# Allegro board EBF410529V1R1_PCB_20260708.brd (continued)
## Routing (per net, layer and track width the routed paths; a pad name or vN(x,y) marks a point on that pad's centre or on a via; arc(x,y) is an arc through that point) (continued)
MIPI_DPHY_CSI3_RX_D0P: length 78.5
  TOP w0.107: J18.11 6.56,55.37 7.29,55.37 arc(7.35,55.38) 7.4,55.42 7.42,55.43 arc(7.47,55.46) 7.53,55.48 11.25,55.48 arc(11.96,55.34) 12.56,54.93 12.89,54.6 arc(13.3,54) 13.44,53.29 13.44,52.3 arc(13.49,52.02) 13.65,51.78 15.72,49.71 arc(16.2,49.51) 16.67,49.71 17.01,50.05 arc(17.19,50.12) 17.37,50.05 arc(17.45,49.85) 17.37,49.65 17.04,49.32 arc(16.85,48.86) 17.04,48.39 17.06,48.37 arc(17.52,48.18) 17.98,48.37 19.44,49.83 arc(19.63,49.91) 19.82,49.83 arc(19.9,49.64) 19.82,49.45 18.29,47.92 arc(18.13,47.53) 18.29,47.14 18.29,47.14 arc(18.64,46.9) 19.06,46.82 19.62,46.82 arc(19.78,46.79) 19.92,46.7 v1(20.06,46.56) ; J3.184 v1(62.19,62.44)
  ART03 w0.102: v1(62.19,62.44) 62.19,62.33 arc(62.21,62.25) 62.25,62.18 62.5,61.93 arc(62.58,61.81) 62.61,61.67 62.61,58.51 arc(62.47,57.79) 62.06,57.19 54.87,49.99 arc(54.53,49.76) 54.12,49.68 25.3,49.68 arc(24.63,49.55) 24.06,49.17 22.9,48.01 arc(22.48,47.72) 21.98,47.62 21.85,47.62 arc(21.5,47.55) 21.2,47.35 20.85,47.01 arc(20.64,46.87) 20.41,46.82 arc(20.33,46.81) 20.26,46.76 v1(20.06,46.56)
MIPI_DPHY_CSI3_RX_D1N: length 80.2
  TOP w0.107: J18.8 7.29,53.87 arc(7.35,53.86) 7.4,53.82 7.42,53.81 arc(7.47,53.77) 7.53,53.76 8.36,53.76 arc(8.74,53.6) 8.91,53.21 8.91,53.01 arc(8.98,52.84) 9.16,52.76 9.17,52.76 arc(9.36,52.84) 9.44,53.03 9.44,53.21 arc(9.6,53.6) 9.99,53.76 11.17,53.76 arc(11.54,53.69) 11.84,53.48 11.86,53.47 arc(12.07,53.16) 12.14,52.8 12.14,52.01 arc(12.25,51.45) 12.56,50.99 12.72,50.83 arc(12.9,50.4) 12.72,49.97 12.44,49.69 arc(12.36,49.5) 12.44,49.31 arc(12.62,49.23) 12.81,49.31 13.1,49.6 arc(13.53,49.77) 13.95,49.6 17.12,46.43 arc(17.35,45.87) 17.12,45.3 16.6,44.78 arc(16.52,44.59) 16.6,44.4 arc(16.8,44.32) 17,44.4 17.69,45.09 arc(18.07,45.25) 18.46,45.09 18.47,45.08 arc(18.67,44.95) 18.91,44.9 19.62,44.9 arc(19.78,44.93) 19.92,45.02 v1(20.06,45.16) ; J3.190 63.69,62.13 v1(63.19,61.63)
  ART03 w0.102: v1(20.06,45.16) 20.22,45 arc(20.39,44.89) 20.59,44.85 21.11,44.85 arc(21.23,44.9) 21.29,45.02 21.29,46.24 arc(21.53,46.82) 22.11,47.07 22.19,47.07 arc(22.64,47.16) 23.03,47.42 24.09,48.48 arc(24.75,48.92) 25.53,49.07 53.89,49.07 arc(54.63,49.22) 55.25,49.64 62.71,57.1 arc(63.16,57.77) 63.32,58.57 63.32,59.65 arc(63.29,59.73) 63.21,59.76 arc(63.13,59.79) 63.09,59.88 63.09,60.05 arc(63.13,60.13) 63.21,60.17 arc(63.29,60.2) 63.32,60.28 63.32,60.46 arc(63.29,60.54) 63.21,60.57 arc(63.13,60.61) 63.09,60.69 63.09,60.87 arc(63.13,60.95) 63.21,60.98 arc(63.29,61.01) 63.32,61.09 63.32,61.42 arc(63.31,61.49) 63.26,61.56 v1(63.19,61.63)
MIPI_DPHY_CSI3_RX_D1P: length 80.1
  TOP w0.107: J18.7 6.56,53.37 7.29,53.37 arc(7.35,53.38) 7.4,53.42 7.42,53.43 arc(7.47,53.46) 7.53,53.48 8.36,53.48 arc(8.54,53.4) 8.62,53.21 8.62,53.01 arc(8.78,52.63) 9.16,52.48 9.17,52.48 arc(9.56,52.64) 9.72,53.03 9.72,53.21 arc(9.8,53.4) 9.99,53.48 11.17,53.48 arc(11.43,53.43) 11.64,53.28 11.66,53.26 arc(11.81,53.05) 11.86,52.8 11.86,52.01 arc(11.99,51.35) 12.36,50.79 12.52,50.63 arc(12.62,50.4) 12.52,50.18 12.23,49.89 arc(12.07,49.5) 12.23,49.11 arc(12.62,48.95) 13.01,49.11 13.3,49.4 arc(13.53,49.49) 13.75,49.4 16.92,46.23 arc(17.07,45.87) 16.92,45.5 16.39,44.98 arc(16.23,44.59) 16.39,44.2 16.4,44.2 arc(16.8,44.03) 17.2,44.2 17.89,44.88 arc(18.07,44.96) 18.26,44.88 18.27,44.88 arc(18.56,44.68) 18.91,44.62 19.85,44.62 arc(20,44.55) 20.06,44.41 v1(20.06,44.35) ; J3.188 v1(63.19,62.44)
  ART03 w0.102: v1(20.06,44.35) 20.17,44.47 arc(20.28,44.54) 20.41,44.57 21.11,44.57 arc(21.43,44.7) 21.56,45.02 21.56,46.24 arc(21.72,46.63) 22.11,46.79 22.19,46.79 arc(22.75,46.9) 23.23,47.22 24.29,48.28 arc(24.86,48.66) 25.53,48.79 53.89,48.79 arc(54.73,48.96) 55.45,49.44 62.91,56.9 arc(63.42,57.67) 63.6,58.57 63.6,61.66 arc(63.58,61.79) 63.5,61.9 63.27,62.13 arc(63.21,62.22) 63.19,62.31 v1(63.19,62.44)
MIPI_DPHY_CSI4_RX_CLKN: length 77.7
  TOP w0.107: v1(60.73,58.48) 60.88,58.63 arc(61.02,58.73) 61.19,58.76 66.66,58.76 arc(67.2,58.87) 67.65,59.17 67.67,59.19 arc(67.98,59.64) 68.08,60.18 68.08,62.47 arc(68.1,62.53) 68.13,62.58 68.14,62.6 arc(68.18,62.65) 68.19,62.71 J3.208
  ART03 w0.102: v1(7.82,38.4) 7.96,38.54 arc(8.04,38.6) 8.13,38.64 arc(8.18,38.64) 8.23,38.63 14.34,38.63 arc(14.83,38.73) 15.25,39.01 18.28,42.04 arc(18.72,42.7) 18.87,43.47 18.87,47.51 arc(18.9,47.65) 18.98,47.77 19.32,48.11 arc(19.8,48.43) 20.36,48.54 21.03,48.54 arc(21.81,48.69) 22.46,49.13 23.57,50.24 arc(24.13,50.62) 24.81,50.75 53.47,50.75 arc(54.12,50.88) 54.67,51.25 59.98,56.55 arc(60.34,57.09) 60.47,57.73 60.47,58.04 arc(60.5,58.2) 60.59,58.34 v1(60.73,58.48)
  BOTTOM w0.107: v1(7.82,38.4) 7.82,38.51 arc(7.78,38.61) 7.67,38.66 7.53,38.66 arc(7.47,38.65) 7.42,38.61 7.4,38.6 arc(7.35,38.56) 7.29,38.55 J17.10
MIPI_DPHY_CSI4_RX_CLKP: length 77.7
  TOP w0.107: v1(59.92,58.48) 60.04,58.48 arc(60.13,58.5) 60.2,58.55 60.4,58.75 arc(60.73,58.97) 61.11,59.04 66.66,59.04 arc(67.09,59.13) 67.45,59.37 67.47,59.39 arc(67.71,59.75) 67.8,60.18 67.8,62.47 arc(67.79,62.53) 67.75,62.58 67.74,62.6 arc(67.7,62.65) 67.69,62.71 J3.206
  ART03 w0.102: v1(7.82,39.2) 8.03,39 arc(8.1,38.94) 8.18,38.92 arc(8.2,38.91) 8.23,38.91 14.34,38.91 arc(14.72,38.99) 15.05,39.21 18.08,42.24 arc(18.46,42.81) 18.59,43.47 18.59,47.51 arc(18.64,47.76) 18.78,47.97 19.12,48.31 arc(19.69,48.69) 20.36,48.82 21.03,48.82 arc(21.7,48.95) 22.27,49.33 23.37,50.43 arc(24.03,50.87) 24.81,51.03 53.47,51.03 arc(54.02,51.14) 54.47,51.44 59.78,56.75 arc(60.08,57.2) 60.19,57.73 60.19,58.04 arc(60.15,58.2) 60.06,58.34 v1(59.92,58.48)
  BOTTOM w0.107: v1(7.82,39.2) 7.82,39.06 arc(7.78,38.98) 7.7,38.94 7.53,38.94 arc(7.47,38.95) 7.42,38.99 7.4,39 arc(7.35,39.04) 7.29,39.05 J17.9
MIPI_DPHY_CSI4_RX_D0N: length 83.9
  TOP w0.107: J3.200 66.19,62.71 arc(66.18,62.65) 66.14,62.6 66.13,62.58 arc(66.1,62.53) 66.08,62.47 66.08,61.98 66.08,61.1 arc(65.94,60.75) 65.59,60.61 60.93,60.61 arc(60.86,60.59) 60.8,60.55 v1(60.73,60.48)
  ART03 w0.102: v1(5.05,37.4) 5.05,37.51 arc(5.06,37.6) 5.11,37.68 5.21,37.77 arc(5.38,37.89) 5.58,37.92 5.67,37.92 arc(5.94,37.98) 6.17,38.13 8.58,40.55 arc(8.69,40.62) 8.81,40.64 12.94,40.64 arc(13.12,40.6) 13.27,40.5 arc(13.5,40.4) 13.75,40.36 13.97,40.36 arc(14.41,40.45) 14.78,40.7 16.63,42.55 arc(17.16,43.34) 17.35,44.28 17.35,47.71 arc(17.48,48.38) 17.86,48.95 18.56,49.65 arc(19.13,50.03) 19.8,50.16 20.67,50.16 arc(20.95,50.22) 21.18,50.37 22.64,51.84 arc(23.21,52.22) 23.88,52.35 41.71,52.35 arc(42.03,52.48) 42.16,52.81 42.16,53.52 arc(42.18,53.61) 42.23,53.69 42.25,53.7 arc(42.32,53.75) 42.41,53.77 42.51,53.77 arc(42.67,53.7) 42.74,53.54 42.74,53.16 arc(43.27,52.63) 43.8,53.16 43.8,53.52 arc(44.06,53.77) 44.31,53.52 44.31,53.16 arc(44.85,52.63) 45.38,53.16 45.38,53.64 arc(45.45,53.82) 45.63,53.9 52.53,53.9 arc(52.63,53.88) 52.72,53.82 53.18,53.36 arc(53.91,53.06) 54.63,53.36 58.1,56.83 arc(58.47,57.38) 58.6,58.04 58.6,59.58 arc(58.64,59.75) 58.73,59.9 58.75,59.91 arc(58.9,60.01) 59.07,60.05 59.87,60.05 arc(60.06,60.08) 60.21,60.19 60.44,60.41 arc(60.52,60.46) 60.61,60.48 v1(60.73,60.48)
  BOTTOM w0.107: J17.12 5.84,37.55 arc(5.77,37.56) 5.71,37.6 5.68,37.63 arc(5.65,37.65) 5.61,37.66 5.31,37.66 arc(5.12,37.58) v1(5.05,37.4)
MIPI_DPHY_CSI4_RX_D0P: length 83.7
  TOP w0.107: v1(59.92,60.48) 60.05,60.48 arc(60.14,60.5) 60.23,60.56 60.47,60.8 arc(60.57,60.87) 60.69,60.89 64.56,60.89 arc(64.65,60.93) 64.68,61.01 arc(64.72,61.1) 64.81,61.14 64.99,61.14 arc(65.07,61.1) 65.11,61.01 arc(65.15,60.93) 65.23,60.89 65.59,60.89 arc(65.74,60.95) 65.8,61.1 65.8,62.47 arc(65.79,62.53) 65.75,62.58 65.74,62.6 arc(65.7,62.65) 65.69,62.71 J3.198
  ART03 w0.102: v1(59.92,60.48) 59.84,60.4 arc(59.76,60.34) 59.66,60.33 59.07,60.33 arc(58.79,60.27) 58.55,60.11 58.54,60.09 arc(58.38,59.86) 58.32,59.58 58.32,59.35 arc(58.29,59.27) 58.21,59.24 arc(58.12,59.2) 58.09,59.12 58.09,58.84 arc(58.12,58.76) 58.21,58.73 arc(58.29,58.69) 58.32,58.61 58.32,58.04 arc(58.21,57.49) 57.91,57.03 54.44,53.56 arc(53.91,53.34) 53.37,53.56 52.92,54.02 arc(52.74,54.14) 52.53,54.18 45.63,54.18 arc(45.26,54.02) 45.1,53.64 45.1,53.16 arc(44.85,52.91) 44.59,53.16 44.59,53.52 arc(44.06,54.05) 43.53,53.52 43.53,53.16 arc(43.27,52.91) 43.02,53.16 43.02,53.54 arc(42.87,53.9) 42.51,54.05 42.41,54.05 arc(42.22,54.01) 42.05,53.9 42.03,53.88 arc(41.92,53.72) 41.88,53.52 41.88,52.81 arc(41.83,52.68) 41.71,52.63 23.88,52.63 arc(23.1,52.47) 22.44,52.03 20.98,50.57 arc(20.84,50.48) 20.67,50.44 19.8,50.44 arc(19.02,50.29) 18.36,49.85 17.66,49.15 arc(17.22,48.49) 17.07,47.71 17.07,44.28 arc(16.9,43.45) 16.43,42.75 14.58,40.89 arc(14.3,40.71) 13.97,40.64 13.75,40.64 arc(13.59,40.66) 13.44,40.72 arc(13.21,40.87) 12.94,40.92 8.81,40.92 arc(8.58,40.87) 8.38,40.74 5.97,38.33 arc(5.83,38.24) 5.67,38.2 v1(5.05,38.2)
  BOTTOM w0.107: v1(5.05,38.2) 5.05,38.16 arc(5.11,38.01) 5.26,37.94 5.61,37.94 arc(5.65,37.95) 5.68,37.97 5.71,38 arc(5.77,38.04) 5.84,38.05 J17.11
MIPI_DPHY_CSI4_RX_D1N: length 83.7
  TOP w0.107: v1(60.73,59.48) 60.8,59.55 arc(60.86,59.59) 60.93,59.61 66.59,59.61 arc(66.94,59.75) 67.08,60.1 67.08,62.47 arc(67.1,62.53) 67.13,62.58 67.14,62.6 arc(67.18,62.65) 67.19,62.71 J3.204
  ART03 w0.102: v1(60.73,59.48) 60.6,59.48 arc(60.51,59.46) 60.42,59.41 60.19,59.17 arc(60.08,59.1) 59.95,59.08 59.74,59.08 arc(59.53,58.99) 59.44,58.78 59.44,57.61 arc(59.34,57.13) 59.07,56.72 54.27,51.92 arc(53.84,51.64) 53.34,51.54 53.14,51.54 arc(52.52,51.79) 52.26,52.42 52.26,52.53 arc(52.01,52.78) 51.75,52.53 51.75,52.07 arc(51.22,51.54) 50.69,52.07 50.69,52.53 arc(50.43,52.78) 50.18,52.53 50.18,52.07 arc(49.65,51.54) 49.11,52.07 49.11,52.53 arc(48.86,52.78) 48.61,52.53 48.61,52.07 arc(48.07,51.54) 47.54,52.07 47.54,52.53 arc(47.28,52.78) 47.03,52.53 47.03,52.07 arc(46.87,51.69) 46.5,51.54 24.31,51.54 arc(23.64,51.4) 23.07,51.02 22,49.95 arc(21.39,49.55) 20.68,49.4 20.21,49.4 arc(19.54,49.27) 18.97,48.89 18.48,48.4 arc(18.21,47.99) 18.11,47.51 18.11,43.8 arc(17.96,43.02) 17.51,42.35 14.87,39.72 arc(14.55,39.5) 14.16,39.42 12.6,39.42 arc(12.4,39.46) 12.22,39.58 arc(12.13,39.64) 12.03,39.66 11.24,39.66 9.26,39.66 arc(9.26,39.66) 9.26,39.66 arc(9.09,39.63) 8.96,39.54 v1(8.82,39.4)
  BOTTOM w0.107: v1(8.82,39.4) 8.68,39.53 arc(8.54,39.63) 8.38,39.66 7.53,39.66 arc(7.47,39.65) 7.42,39.61 7.4,39.6 arc(7.35,39.56) 7.29,39.55 J17.8
MIPI_DPHY_CSI4_RX_D1P: length 83.7
  TOP w0.107: J3.202 66.69,62.71 arc(66.7,62.65) 66.74,62.6 66.75,62.58 arc(66.79,62.53) 66.8,62.47 66.8,61.83 arc(66.77,61.76) 66.7,61.73 arc(66.63,61.7) 66.6,61.63 66.6,61.41 arc(66.63,61.33) 66.7,61.31 arc(66.77,61.28) 66.8,61.21 66.8,60.98 arc(66.77,60.91) 66.7,60.88 arc(66.63,60.85) 66.6,60.78 66.6,60.55 arc(66.63,60.48) 66.7,60.45 arc(66.77,60.42) 66.8,60.35 66.8,60.1 arc(66.74,59.95) 66.59,59.89 60.68,59.89 arc(60.56,59.87) 60.46,59.8 60.21,59.55 arc(60.14,59.5) 60.04,59.48 v1(59.92,59.48)
  ART03 w0.102: v1(8.82,40.2) 8.96,40.06 arc(9.1,39.97) 9.26,39.94 11.24,39.94 12.03,39.94 arc(12.24,39.9) 12.42,39.78 arc(12.51,39.72) 12.6,39.7 14.16,39.7 arc(14.44,39.76) 14.68,39.91 17.32,42.55 arc(17.7,43.12) 17.83,43.8 17.83,47.51 arc(17.95,48.1) 18.28,48.6 18.77,49.09 arc(19.43,49.53) 20.21,49.68 20.68,49.68 arc(21.29,49.8) 21.8,50.15 22.87,51.22 arc(23.53,51.66) 24.31,51.82 46.5,51.82 arc(46.68,51.89) 46.75,52.07 46.75,52.53 arc(47.28,53.06) 47.82,52.53 47.82,52.07 arc(48.07,51.82) 48.33,52.07 48.33,52.53 arc(48.86,53.06) 49.39,52.53 49.39,52.07 arc(49.65,51.82) 49.9,52.07 49.9,52.53 arc(50.43,53.06) 50.97,52.53 50.97,52.07 arc(51.22,51.82) 51.48,52.07 51.48,52.53 arc(52.01,53.06) 52.54,52.53 52.54,52.42 arc(52.72,51.99) 53.14,51.82 53.34,51.82 arc(53.74,51.9) 54.07,52.12 54.44,52.49 58.88,56.92 arc(59.09,57.24) 59.16,57.61 59.16,58.78 arc(59.33,59.19) 59.74,59.36 59.75,59.36 arc(59.79,59.36) 59.83,59.39 v1(59.92,59.48)
  BOTTOM w0.107: v1(8.82,40.2) 8.68,40.07 arc(8.54,39.97) 8.38,39.94 7.53,39.94 arc(7.47,39.95) 7.42,39.99 7.4,40 arc(7.35,40.04) 7.29,40.05 J17.7
MIPI_DPHY_DSI_TX_CLKN: length 100.5
  TOP w0.107: v1(140.38,23.01) 140.38,22.77 arc(140.42,22.66) 140.52,22.62 140.83,22.62 arc(140.93,22.66) 140.97,22.76 140.97,22.95 arc(141.04,23.32) 141.25,23.64 141.27,23.66 arc(141.58,23.86) 141.95,23.94 142.52,23.94 arc(142.58,23.95) 142.63,23.98 142.65,24 arc(142.7,24.03) 142.76,24.05 J13.24 ; J3.274 84.69,62.73 arc(84.68,62.65) 84.63,62.59 84.62,62.57 arc(84.58,62.51) 84.56,62.44 84.56,61.57 arc(84.6,61.48) v1(84.69,61.44)
  ART03 w0.102: v1(84.69,61.44) 84.69,61.31 arc(84.71,61.22) 84.77,61.13 85,60.9 arc(85.08,60.77) 85.12,60.61 85.12,60.43 86.56,58.98 arc(87.13,58.6) 87.8,58.47 91.67,58.47 arc(92.29,58.35) 92.82,57.99 93.49,57.32 94.06,56.75 arc(94.08,56.74) 94.09,56.73 arc(94.57,56.42) 95.13,56.31 111.02,56.31 arc(111.8,56.16) 112.46,55.72 125.08,43.09 arc(125.52,42.43) 125.68,41.65 125.68,41.1 arc(125.97,40.39) 126.68,40.1 127.13,40.1 arc(127.66,39.56) 127.13,39.03 125.93,39.03 arc(125.75,38.95) 125.68,38.77 125.68,38.75 arc(125.75,38.57) 125.93,38.5 126.57,38.5 arc(127.1,37.96) 126.57,37.43 125.93,37.43 arc(125.75,37.35) 125.68,37.17 125.68,37.05 arc(125.78,36.8) 126.03,36.69 127.13,36.69 arc(127.66,36.16) 127.13,35.62 125.93,35.62 arc(125.68,35.37) 125.93,35.12 126.97,35.12 arc(127.51,34.58) 126.97,34.05 125.93,34.05 arc(125.75,33.98) 125.68,33.8 125.68,33.57 arc(125.74,33.43) 125.87,33.38 126.97,33.38 arc(127.41,33.2) 127.58,32.77 127.58,32.68 arc(127.39,32.2) 126.91,32 126.59,32 arc(126.34,31.75) 126.59,31.5 127.05,31.5 arc(127.58,30.96) 127.05,30.43 126.72,30.43 arc(126.47,30.18) 126.72,29.92 127.1,29.92 arc(127.48,29.76) 127.64,29.39 127.64,29.29 arc(127.68,29.07) 127.8,28.9 131.74,24.95 arc(132.29,24.59) 132.93,24.46 133.09,24.46 arc(133.81,24.32) 134.43,23.91 134.52,23.82 arc(135.04,23.47) 135.66,23.34 137.97,23.34 arc(138.42,23.25) 138.8,23 138.9,22.9 arc(139.13,22.75) 139.39,22.69 140.09,22.69 arc(140.29,22.78) 140.38,22.98 v1(140.38,23.01)
MIPI_DPHY_DSI_TX_CLKP: length 100.5
  TOP w0.107: J3.272 84.19,62.7 arc(84.2,62.65) 84.23,62.61 84.24,62.6 arc(84.27,62.56) 84.28,62.51 84.28,61.39 arc(84.3,61.27) 84.37,61.17 84.62,60.92 arc(84.67,60.84) 84.69,60.75 v1(84.69,60.63) ; v1(140.38,22.2) 140.45,22.28 arc(140.52,22.32) 140.6,22.34 140.83,22.34 arc(141.13,22.46) 141.25,22.76 141.25,22.95 arc(141.31,23.21) 141.45,23.44 141.47,23.45 arc(141.69,23.6) 141.95,23.65 142.52,23.65 arc(142.58,23.64) 142.63,23.61 142.65,23.59 arc(142.7,23.56) 142.76,23.55 J13.23
  ART03 w0.102: v1(140.38,22.2) 140.29,22.29 arc(140.22,22.35) 140.14,22.39 139.99,22.41 139.39,22.41 arc(139.02,22.49) 138.7,22.7 138.6,22.8 arc(138.31,22.99) 137.97,23.06 135.66,23.06 arc(134.93,23.21) 134.32,23.62 134.23,23.71 arc(133.71,24.06) 133.09,24.18 132.93,24.18 arc(132.18,24.33) 131.54,24.76 127.6,28.7 arc(127.42,28.97) 127.36,29.29 127.36,29.39 arc(127.28,29.57) 127.1,29.64 126.72,29.64 arc(126.19,30.18) 126.72,30.71 127.05,30.71 arc(127.3,30.96) 127.05,31.22 126.59,31.22 arc(126.06,31.75) 126.59,32.28 126.91,32.28 arc(127.19,32.4) 127.3,32.68 127.3,32.77 arc(127.21,33) 126.97,33.1 125.87,33.1 arc(125.54,33.23) 125.4,33.57 125.4,33.8 arc(125.56,34.17) 125.93,34.33 126.97,34.33 arc(127.23,34.58) 126.97,34.84 125.93,34.84 arc(125.4,35.37) 125.93,35.9 127.13,35.9 arc(127.38,36.16) 127.13,36.41 126.03,36.41 arc(125.59,36.6) 125.4,37.05 125.4,37.17 arc(125.56,37.55) 125.93,37.71 126.57,37.71 arc(126.82,37.96) 126.57,38.22 125.93,38.22 arc(125.56,38.37) 125.4,38.75 125.4,38.77 arc(125.56,39.15) 125.93,39.31 127.13,39.31 arc(127.38,39.56) 127.13,39.82 126.68,39.82 arc(125.78,40.19) 125.4,41.1 125.4,41.65 arc(125.27,42.32) 124.89,42.89 112.26,55.52 arc(111.69,55.9) 111.02,56.03 95.13,56.03 arc(94.46,56.16) 93.9,56.52 93.9,56.52 92.62,57.8 arc(92.18,58.09) 91.67,58.19 87.8,58.19 arc(87.02,58.35) 86.36,58.79 84.84,60.31 84.84,60.41 arc(84.82,60.48) 84.78,60.54 v1(84.69,60.63)
MIPI_DPHY_DSI_TX_D0N: length 100.5
  TOP w0.107: v1(141.8,25.7) 141.8,25.55 arc(141.83,25.47) 141.91,25.44 142.52,25.44 arc(142.58,25.45) 142.63,25.48 142.65,25.5 arc(142.7,25.53) 142.76,25.55 J13.27 ; J3.282 86.69,62.74 arc(86.67,62.65) 86.62,62.58 86.61,62.56 arc(86.56,62.49) 86.54,62.4 86.54,61.59 arc(86.59,61.48) v1(86.69,61.44)
  ART03 w0.102: v1(141.8,25.7) 141.83,25.67 141.83,25.58 arc(141.76,25.4) 141.57,25.32 140.07,25.32 arc(139.89,25.4) 139.82,25.58 139.82,25.7 arc(139.28,26.24) 138.75,25.7 138.75,25.57 arc(138.68,25.39) 138.51,25.32 138.5,25.32 arc(138.32,25.4) 138.24,25.58 138.24,25.7 arc(137.71,26.24) 137.18,25.7 137.18,25.5 arc(137.12,25.38) 137,25.32 136.4,25.32 arc(136.22,25.36) 136.07,25.46 135.58,25.95 arc(135.49,26.17) 135.58,26.4 135.83,26.64 arc(135.98,27.02) 135.83,27.39 arc(135.45,27.55) 135.07,27.39 134.78,27.11 arc(134.43,27.11) 134.43,27.47 134.71,27.75 arc(134.87,28.13) 134.71,28.51 arc(134.33,28.66) 133.96,28.51 133.67,28.22 arc(133.31,28.22) 133.31,28.58 133.6,28.87 arc(133.75,29.24) 133.6,29.62 arc(133.22,29.78) 132.84,29.62 132.56,29.33 arc(132.2,29.33) 132.2,29.69 132.48,29.98 arc(132.64,30.36) 132.48,30.74 arc(132.11,30.89) 131.73,30.74 131.46,30.47 arc(131.26,30.39) 131.07,30.47 131.05,30.49 arc(130.82,30.83) 130.73,31.24 130.73,33.99 arc(130.81,34.17) 130.99,34.24 131.52,34.24 arc(132.07,34.79) 131.52,35.33 131.28,35.33 arc(130.89,35.49) 130.73,35.88 130.73,37.17 arc(130.81,37.35) 130.99,37.42 131.41,37.42 arc(131.95,37.96) 131.41,38.49 130.99,38.49 arc(130.73,38.74) 130.99,39 131.41,39 arc(131.95,39.53) 131.41,40.06 130.99,40.06 arc(130.81,40.14) 130.73,40.32 130.73,40.32 arc(130.68,40.58) 130.54,40.8 128.73,42.61 arc(128.65,42.79) 128.73,42.97 128.9,43.14 arc(129.06,43.52) 128.9,43.9 128.89,43.9 arc(128.52,44.06) 128.16,43.9 127.97,43.72 arc(127.61,43.72) 127.61,44.08 127.79,44.25 arc(127.94,44.63) 127.79,45.01 127.78,45.02 arc(127.41,45.17) 127.04,45.02 126.86,44.84 arc(126.5,44.84) 126.5,45.2 126.67,45.37 arc(126.83,45.75) 126.67,46.12 126.66,46.13 arc(126.3,46.28) 125.93,46.13 125.75,45.95 arc(125.39,45.95) 125.39,46.31 125.56,46.48 arc(125.72,46.86) 125.56,47.24 125.55,47.25 arc(125.18,47.4) 124.81,47.25 124.63,47.06 arc(124.45,46.99) 124.27,47.06 114.02,57.32 arc(113.36,57.76) 112.58,57.91 95.62,57.91 arc(95.31,57.97) 95.06,58.14 93.73,59.47 arc(93.15,59.86) 92.47,59.99 88.08,59.99 arc(87.75,60.06) 87.47,60.25 87.12,60.68 87.12,60.7 arc(87.11,60.78) 87.06,60.84 86.76,61.14 arc(86.71,61.22) 86.69,61.32 v1(86.69,61.44)
MIPI_DPHY_DSI_TX_D0P: length 100.5
  TOP w0.107: J13.26 142.76,25.05 arc(142.7,25.06) 142.65,25.09 142.63,25.11 arc(142.58,25.14) 142.52,25.15 142.24,25.15 arc(142.08,25.12) 141.94,25.03 v1(141.8,24.89) ; v1(86.69,60.63) 86.69,60.74 arc(86.67,60.83) 86.63,60.9 86.41,61.11 arc(86.3,61.28) 86.26,61.48 86.26,62.58 86.19,62.65 J3.280
  ART03 w0.102: v1(86.69,60.63) 87.27,60.05 arc(87.64,59.8) 88.08,59.72 92.47,59.72 arc(93.04,59.6) 93.53,59.27 94.86,57.94 arc(95.21,57.71) 95.62,57.63 112.58,57.63 arc(113.25,57.5) 113.82,57.12 124.08,46.87 arc(124.45,46.71) 124.83,46.87 125.01,47.05 arc(125.18,47.12) 125.35,47.05 125.36,47.04 arc(125.44,46.86) 125.36,46.68 125.19,46.51 arc(125.19,45.75) 125.94,45.75 126.13,45.93 arc(126.3,46) 126.47,45.93 126.48,45.93 arc(126.55,45.75) 126.48,45.57 126.3,45.39 arc(126.3,44.64) 127.06,44.64 127.24,44.82 arc(127.41,44.89) 127.58,44.82 127.59,44.81 arc(127.66,44.63) 127.59,44.45 127.42,44.28 arc(127.42,43.53) 128.17,43.53 128.35,43.71 arc(128.52,43.78) 128.69,43.71 128.7,43.7 arc(128.78,43.52) 128.7,43.34 128.53,43.17 arc(128.37,42.79) 128.53,42.41 130.34,40.6 arc(130.42,40.48) 130.45,40.32 130.45,40.32 arc(130.61,39.94) 130.99,39.78 131.41,39.78 arc(131.67,39.53) 131.41,39.28 130.99,39.28 arc(130.45,38.74) 130.99,38.21 131.41,38.21 arc(131.67,37.96) 131.41,37.7 130.99,37.7 arc(130.61,37.55) 130.45,37.17 130.45,35.88 arc(130.7,35.3) 131.28,35.05 131.52,35.05 arc(131.79,34.79) 131.52,34.52 130.99,34.52 arc(130.61,34.36) 130.45,33.99 130.45,31.24 arc(130.56,30.73) 130.85,30.29 130.87,30.27 arc(131.26,30.11) 131.66,30.27 131.93,30.54 arc(132.11,30.61) 132.29,30.54 arc(132.36,30.36) 132.29,30.18 132,29.89 arc(132,29.14) 132.75,29.14 133.04,29.42 arc(133.22,29.5) 133.4,29.42 arc(133.48,29.24) 133.4,29.07 133.11,28.78 arc(133.11,28.02) 133.87,28.02 134.16,28.31 arc(134.33,28.39) 134.51,28.31 arc(134.59,28.13) 134.51,27.95 134.23,27.66 arc(134.23,26.91) 134.98,26.91 135.27,27.2 arc(135.45,27.27) 135.63,27.2 135.63,27.2 arc(135.7,27.02) 135.63,26.84 135.39,26.6 arc(135.21,26.17) 135.39,25.75 135.87,25.26 arc(136.12,25.1) 136.4,25.04 137,25.04 arc(137.32,25.18) 137.46,25.5 137.46,25.7 arc(137.71,25.96) 137.96,25.7 137.96,25.58 arc(138.12,25.2) 138.5,25.04 138.51,25.04 arc(138.88,25.2) 139.03,25.57 139.03,25.7 arc(139.28,25.96) 139.54,25.7 139.54,25.58 arc(139.69,25.2) 140.07,25.04 141.55,25.04 arc(141.64,25.03) 141.72,24.98 v1(141.8,24.89)
MIPI_DPHY_DSI_TX_D1N: length 100.6
  TOP w0.107: J13.21 142.76,22.55 arc(142.7,22.53) 142.65,22.5 142.63,22.48 arc(142.58,22.45) 142.52,22.44 141.91,22.44 arc(141.83,22.47) 141.8,22.55 v1(141.8,22.7) ; J3.278 85.69,62.73 arc(85.67,62.65) 85.63,62.58 85.61,62.57 arc(85.57,62.5) 85.55,62.42 85.55,61.58 arc(85.59,61.48) v1(85.69,61.44)
  ART03 w0.102: v1(85.69,61.44) 85.69,61.32 arc(85.71,61.23) 85.76,61.15 86.01,60.9 arc(86.08,60.8) 86.11,60.67 86.11,60.52 86.93,59.7 arc(87.44,59.35) 88.05,59.23 92.15,59.23 arc(92.77,59.11) 93.31,58.75 94.5,57.56 arc(94.95,57.26) 95.49,57.15 111.83,57.15 arc(112.61,57) 113.27,56.55 126.31,43.52 arc(126.48,43.26) 126.54,42.95 126.54,42.85 arc(126.62,42.67) 126.8,42.6 127.34,42.6 arc(127.69,42.45) 127.84,42.1 127.84,42.08 arc(127.69,41.73) 127.34,41.58 126.87,41.58 arc(126.64,41.49) 126.54,41.25 126.54,41.02 arc(126.58,40.93) 126.67,40.89 128.15,40.89 arc(128.47,40.76) 128.6,40.45 128.6,40.24 arc(128.67,40.06) 128.85,39.99 129.26,39.99 arc(129.79,39.45) 129.26,38.92 128.85,38.92 arc(128.6,38.67) 128.85,38.41 129.26,38.41 arc(129.79,37.88) 129.26,37.34 128.85,37.34 arc(128.67,37.27) 128.6,37.09 128.6,35.95 arc(128.67,35.77) 128.85,35.7 129.29,35.7 arc(129.82,35.16) 129.29,34.63 129.25,34.63 arc(128.79,34.44) 128.6,33.98 128.6,33.55 arc(128.67,33.37) 128.85,33.3 129.07,33.3 arc(129.4,33.16) 129.54,32.83 129.54,32.8 arc(129.38,32.4) 128.98,32.23 128.85,32.23 arc(128.67,32.16) 128.6,31.98 128.6,31.08 129.14,30.54 arc(129.31,30.12) 129.14,29.69 128.89,29.45 arc(128.82,29.27) 128.89,29.09 128.9,29.08 arc(129.07,29.01) 129.24,29.08 129.75,29.59 arc(130.53,29.59) 130.53,28.81 130.18,28.46 arc(130.18,28.46) 130.18,28.45 arc(130.11,28.28) 130.18,28.1 130.19,28.09 arc(130.36,28.02) 130.53,28.09 130.89,28.44 arc(131.64,28.44) 131.64,27.69 131.14,27.19 arc(131.07,27.03) 131.14,26.86 131.17,26.83 arc(131.34,26.76) 131.5,26.83 131.88,27.21 arc(132.43,27.44) 132.97,27.21 133.01,27.17 arc(133.25,26.6) 133.01,26.03 132.71,25.73 arc(132.71,25.37) 133.07,25.37 133.35,25.65 arc(133.69,25.79) 134.03,25.65 134.65,25.02 arc(135.22,24.64) 135.89,24.51 139.75,24.51 arc(140.3,24.4) 140.77,24.09 140.81,24.05 arc(141.11,23.6) 141.21,23.08 141.21,22.5 arc(141.27,22.36) 141.42,22.3 141.66,22.3 arc(141.71,22.31) 141.75,22.33 141.76,22.35 arc(141.79,22.39) 141.8,22.44 v1(141.8,22.7)
MIPI_DPHY_DSI_TX_D1P: length 100.6
  TOP w0.107: J3.276 85.19,62.65 85.27,62.57 85.27,61.48 arc(85.31,61.28) 85.42,61.11 85.62,60.91 arc(85.67,60.83) 85.69,60.75 v1(85.69,60.63) ; J13.20 142.76,22.05 arc(142.7,22.06) 142.65,22.09 142.63,22.11 arc(142.58,22.14) 142.52,22.15 142.24,22.15 arc(142.08,22.12) 141.94,22.03 v1(141.8,21.89)
  ART03 w0.102: v1(141.8,21.89) 141.73,21.96 arc(141.67,22) 141.59,22.02 141.42,22.02 arc(141.08,22.16) 140.93,22.5 140.93,23.08 arc(140.85,23.5) 140.62,23.85 140.57,23.89 arc(140.2,24.14) 139.75,24.23 135.89,24.23 arc(135.12,24.39) 134.46,24.83 133.83,25.45 arc(133.69,25.51) 133.55,25.45 133.27,25.17 arc(132.51,25.17) 132.51,25.92 132.82,26.23 arc(132.97,26.6) 132.82,26.97 132.78,27.02 arc(132.43,27.16) 132.08,27.02 131.7,26.63 arc(131.34,26.48) 130.97,26.63 130.95,26.66 arc(130.79,27.03) 130.95,27.39 131.44,27.89 arc(131.44,28.25) 131.08,28.25 130.73,27.89 arc(130.36,27.74) 130,27.89 129.98,27.9 arc(129.83,28.27) 129.98,28.65 arc(129.98,28.65) 129.98,28.66 130.34,29.01 arc(130.34,29.39) 129.95,29.39 129.44,28.88 arc(129.07,28.73) 128.7,28.88 128.69,28.89 arc(128.54,29.27) 128.69,29.64 128.94,29.89 arc(129.03,30.12) 128.94,30.35 128.32,30.96 128.32,31.98 arc(128.48,32.36) 128.85,32.51 128.98,32.51 arc(129.18,32.59) 129.26,32.8 129.26,32.83 arc(129.2,32.96) 129.07,33.02 128.85,33.02 arc(128.48,33.18) 128.32,33.55 128.32,33.98 arc(128.59,34.64) 129.25,34.91 129.29,34.91 arc(129.54,35.16) 129.29,35.42 128.85,35.42 arc(128.48,35.57) 128.32,35.95 128.32,37.09 arc(128.48,37.47) 128.85,37.62 129.26,37.62 arc(129.51,37.88) 129.26,38.13 128.85,38.13 arc(128.32,38.67) 128.85,39.2 129.26,39.2 arc(129.51,39.45) 129.26,39.71 128.85,39.71 arc(128.48,39.86) 128.32,40.24 128.32,40.45 arc(128.27,40.57) 128.15,40.61 126.67,40.61 arc(126.38,40.73) 126.26,41.02 126.26,41.25 arc(126.44,41.68) 126.87,41.86 127.34,41.86 arc(127.5,41.93) 127.56,42.08 127.56,42.1 arc(127.5,42.26) 127.34,42.32 126.8,42.32 arc(126.42,42.48) 126.26,42.85 126.26,42.95 arc(126.22,43.15) 126.11,43.32 113.07,56.36 arc(112.5,56.74) 111.83,56.87 95.49,56.87 arc(94.85,57) 94.3,57.36 93.11,58.56 arc(92.67,58.85) 92.15,58.95 88.05,58.95 arc(87.33,59.1) 86.73,59.5 85.83,60.4 85.83,60.5 v1(85.69,60.63)
MIPI_DPHY_DSI_TX_D2N: length 100.5
  TOP w0.107: v1(140.45,21.2) 140.45,21.05 arc(140.48,20.97) 140.56,20.94 142.55,20.94 arc(142.61,20.95) 142.66,20.98 142.67,21 arc(142.72,21.03) 142.78,21.05 J13.18 ; J3.268 83.19,62.71 arc(83.18,62.65) 83.14,62.6 83.13,62.58 arc(83.1,62.53) 83.08,62.47 83.08,62.05 v1(83.69,61.44)
  ART03 w0.102: v1(140.45,21.2) 140.49,21.17 140.49,21.03 arc(140.42,20.87) 140.27,20.81 139.79,20.81 arc(139.54,20.86) 139.32,21.01 138.8,21.53 arc(138.14,21.97) 137.36,22.12 135.39,22.12 arc(134.71,22.26) 134.15,22.64 133.91,22.87 arc(133.25,23.31) 132.47,23.47 132.2,23.47 arc(131.53,23.6) 130.96,23.98 124.75,30.19 arc(124.62,30.5) 124.75,30.81 125.12,31.18 arc(125.26,31.52) 125.12,31.86 125.08,31.9 arc(124.7,32.05) 124.33,31.9 123.86,31.44 arc(123.68,31.36) 123.5,31.44 arc(123.38,31.61) 123.34,31.83 123.34,32.21 arc(123.51,32.62) 123.93,32.79 124.18,32.79 arc(124.71,33.32) 124.18,33.86 123.6,33.86 arc(123.34,34.11) 123.6,34.36 124.28,34.36 arc(124.82,34.9) 124.28,35.43 123.6,35.43 arc(123.34,35.68) 123.6,35.94 124.28,35.94 arc(124.82,36.47) 124.28,37 123.6,37 arc(123.34,37.26) 123.6,37.51 124.28,37.51 arc(124.82,38.05) 124.28,38.58 123.6,38.58 arc(123.34,38.83) 123.6,39.09 124.21,39.09 arc(124.74,39.62) 124.21,40.15 123.6,40.15 arc(123.42,40.23) 123.34,40.41 123.34,41.03 arc(123.42,41.21) 123.6,41.29 123.83,41.29 arc(124.17,41.43) 124.31,41.77 124.31,41.82 arc(124.15,42.2) 123.77,42.35 123.6,42.35 arc(123.42,42.43) 123.34,42.61 123.34,42.68 arc(123.28,42.99) 123.11,43.25 111.48,54.88 arc(110.82,55.32) 110.04,55.47 94.67,55.47 arc(94.1,55.59) 93.61,55.92 92.31,57.21 arc(91.82,57.54) 91.23,57.66 87.44,57.66 arc(86.77,57.79) 86.2,58.17 84.26,60.11 arc(84.23,60.15) 84.23,60.2 84.23,60.22 arc(84.1,60.85) 83.74,61.39 v1(83.69,61.44)
MIPI_DPHY_DSI_TX_D2P: length 100.5
  TOP w0.107: v1(140.45,20.39) 140.59,20.53 arc(140.73,20.62) 140.89,20.65 142.54,20.65 arc(142.61,20.64) 142.66,20.61 142.67,20.59 arc(142.72,20.56) 142.78,20.55 J13.17 ; J3.266 82.69,62.71 arc(82.7,62.65) 82.74,62.6 82.75,62.58 arc(82.79,62.53) 82.8,62.47 82.8,61.93 83.26,61.47 83.26,61.37 arc(83.28,61.3) 83.32,61.24 83.62,60.93 arc(83.67,60.85) 83.69,60.76 v1(83.69,60.63)
  ART03 w0.102: v1(140.45,20.39) 140.38,20.47 arc(140.31,20.51) 140.23,20.53 139.79,20.53 arc(139.43,20.6) 139.12,20.81 138.6,21.33 arc(138.03,21.71) 137.36,21.84 135.39,21.84 arc(134.61,22) 133.95,22.44 133.71,22.68 arc(133.14,23.06) 132.47,23.19 132.2,23.19 arc(131.42,23.34) 130.76,23.79 124.55,29.99 arc(124.34,30.5) 124.55,31.01 124.92,31.38 arc(124.98,31.52) 124.92,31.66 124.88,31.7 arc(124.7,31.78) 124.52,31.7 124.06,31.24 arc(123.68,31.08) 123.31,31.24 arc(123.13,31.51) 123.06,31.83 123.06,32.21 arc(123.32,32.82) 123.93,33.07 124.18,33.07 arc(124.43,33.32) 124.18,33.58 123.6,33.58 arc(123.06,34.11) 123.6,34.64 124.28,34.64 arc(124.54,34.9) 124.28,35.15 123.6,35.15 arc(123.06,35.68) 123.6,36.22 124.28,36.22 arc(124.54,36.47) 124.28,36.73 123.6,36.73 arc(123.06,37.26) 123.6,37.79 124.28,37.79 arc(124.54,38.05) 124.28,38.3 123.6,38.3 arc(123.06,38.83) 123.6,39.37 124.21,39.37 arc(124.46,39.62) 124.21,39.88 123.6,39.88 arc(123.22,40.03) 123.06,40.41 123.06,41.03 arc(123.22,41.41) 123.6,41.57 123.83,41.57 arc(123.97,41.63) 124.03,41.77 124.03,41.82 arc(123.95,42) 123.77,42.07 123.6,42.07 arc(123.22,42.23) 123.06,42.61 123.06,42.68 arc(123.02,42.88) 122.91,43.05 111.28,54.68 arc(110.71,55.06) 110.04,55.19 94.67,55.19 arc(93.99,55.33) 93.41,55.72 92.12,57.01 arc(91.71,57.28) 91.23,57.38 87.44,57.38 arc(86.66,57.53) 86,57.97 84.06,59.92 arc(83.98,60.05) 83.95,60.2 83.95,60.21 arc(83.92,60.36) 83.83,60.49 v1(83.69,60.63)
MIPI_DPHY_DSI_TX_D3N: length 100.5
  TOP w0.107: v1(146.11,20.48) 146.05,20.54 arc(146.02,20.59) 146,20.65 146,21 arc(146.05,21.22) 146.18,21.42 146.45,21.69 arc(146.62,21.95) 146.69,22.26 146.69,23.49 arc(146.38,25) 145.53,26.28 145.08,26.73 arc(144.88,26.87) 144.64,26.91 144.51,26.91 arc(144.43,26.93) 144.37,26.97 144.35,26.99 arc(144.28,27.03) 144.21,27.05 J13.30 ; J3.264 82.19,62.71 arc(82.18,62.65) 82.14,62.6 82.13,62.58 arc(82.1,62.53) 82.08,62.47 82.08,61.52 arc(82.14,61.38) 82.29,61.32 82.5,61.32 arc(82.57,61.33) 82.62,61.37 v1(82.69,61.44)
  ART03 w0.102: v1(146.11,20.48) 146.05,20.41 arc(146.01,20.36) 146,20.29 146,20.23 arc(145.97,20.05) 145.87,19.91 145.62,19.66 arc(145.22,19.4) 144.75,19.3 139.96,19.3 arc(139.18,19.46) 138.52,19.9 138.23,20.19 arc(137.66,20.57) 137,20.7 136.04,20.7 arc(134.4,21.03) 133.01,21.96 arc(132.82,22.08) 132.61,22.12 131.24,22.12 arc(130.58,22.25) 130.03,22.62 123.06,29.6 arc(122.28,30.76) 122.01,32.13 122.01,40.76 arc(121.7,42.28) 120.84,43.58 110.69,53.72 arc(110.07,54.14) 109.35,54.28 106.59,54.28 arc(106.45,54.25) 106.34,54.18 106.25,54.08 arc(106.04,53.95) 105.8,53.9 94.46,53.9 arc(94,53.99) 93.62,54.25 91.53,56.33 arc(91.22,56.54) 90.84,56.62 86.93,56.62 arc(86.16,56.77) 85.5,57.21 82.4,60.31 arc(82.31,60.45) 82.27,60.61 82.27,60.63 arc(82.31,60.8) 82.4,60.94 82.62,61.16 arc(82.67,61.23) 82.69,61.32 v1(82.69,61.44)
MIPI_DPHY_DSI_TX_D3P: length 100.4
  TOP w0.107: J13.29 144.24,26.55 arc(144.29,26.55) 144.32,26.58 144.34,26.59 arc(144.38,26.62) 144.42,26.63 144.64,26.63 arc(144.77,26.6) 144.87,26.53 145.33,26.08 arc(146.12,24.89) 146.4,23.49 146.4,22.26 arc(146.36,22.06) 146.25,21.89 145.98,21.62 arc(145.79,21.33) 145.72,21 145.72,20.62 arc(145.68,20.52) 145.57,20.48 v1(145.31,20.48) ; v1(82.69,60.63) 82.69,60.9 arc(82.65,61) 82.55,61.04 82.29,61.04 arc(81.94,61.18) 81.8,61.52 81.8,62.47 arc(81.79,62.53) 81.75,62.58 81.74,62.6 arc(81.7,62.65) 81.69,62.71 J3.262
  ART03 w0.102: v1(82.69,60.63) 82.69,60.51 arc(82.71,60.42) 82.76,60.34 82.92,60.18 arc(82.99,60.16) 83.05,60.18 arc(83.14,60.22) 83.23,60.18 83.41,60 arc(83.45,59.91) 83.41,59.82 arc(83.38,59.76) 83.41,59.7 85.69,57.41 arc(86.26,57.03) 86.93,56.9 90.84,56.9 arc(91.32,56.8) 91.73,56.53 93.82,54.44 arc(94.11,54.25) 94.46,54.18 105.8,54.18 arc(105.93,54.21) 106.05,54.28 106.14,54.37 arc(106.34,54.51) 106.59,54.56 109.35,54.56 arc(110.18,54.39) 110.89,53.92 121.04,43.77 arc(121.96,42.39) 122.29,40.76 122.29,32.13 arc(122.54,30.87) 123.25,29.8 130.23,22.82 arc(130.69,22.51) 131.24,22.4 132.61,22.4 arc(132.93,22.34) 133.21,22.15 arc(134.51,21.29) 136.04,20.98 137,20.98 arc(137.77,20.83) 138.43,20.39 138.72,20.1 arc(139.29,19.72) 139.96,19.58 140.19,19.58 arc(140.28,19.62) 140.33,19.72 arc(140.37,19.82) 140.47,19.86 140.69,19.86 arc(140.79,19.82) 140.83,19.72 arc(140.87,19.62) 140.97,19.58 141.31,19.58 arc(141.41,19.62) 141.45,19.72 arc(141.49,19.82) 141.59,19.86 141.82,19.86 arc(141.92,19.82) 141.96,19.72 arc(142,19.62) 142.1,19.58 144.75,19.58 arc(145.12,19.66) 145.42,19.86 145.67,20.11 arc(145.71,20.16) 145.72,20.23 145.72,20.32 arc(145.67,20.43) 145.56,20.48 v1(145.31,20.48)
ON/OFF: length 27.4
  BOTTOM w0.107: R31.1 C30.1 129.95,66.32 D13.2 131.81,69.16 138.94,69.16 142.52,72.75 142.52,79.65 SW3.2
PCIE0_CLKREQN_M0: length 95.7
  TOP w0.132: J3.139 48.94,54.23 49.43,53.75 49.43,30.61 v1(49.99,30.05) ; R181.1 v1(108.84,11.42)
  BOTTOM w0.132: v1(108.84,11.42) 107.93,10.52 99.95,10.52 93.12,17.35 67.92,17.35 67.18,18.08 59.59,18.08 54.76,22.91 54.76,25.27 v1(49.99,30.05)
PCIE0_PERSTN: length 178.3
  TOP w0.107: v1(49.94,53.54) 49.94,53.84 49.44,54.34 J3.141 ; R183.2 126.61,23.61 v1(126.61,24.61)
  BOTTOM w0.107: v1(126.61,24.61) 128.67,26.67 137.11,26.67 138.28,25.5 139.37,25.5 141.02,23.85 146.2,23.85 147.62,22.43 147.62,9.14 146.79,8.31 137.72,8.31 136.94,7.52 135.1,7.52 134.29,8.33 112.65,8.33 111.28,9.7 90.42,9.7 88.52,11.61 88.52,14.15 86.84,15.82 75.36,15.82 73.39,13.86 67.27,13.86 65.25,15.88 61.93,15.88 60.55,17.25 59.26,17.25 52.83,23.67 52.83,26.09 49.25,29.67 49.25,31.83 50.16,32.74 50.16,53.32 v1(49.94,53.54)
PCIE0_REFCLKN: length 89.6
  TOP w0.107: J3.199 65.44,54.82 arc(65.45,54.75) 65.49,54.7 65.51,54.68 arc(65.54,54.62) 65.56,54.56 65.56,46.43 arc(66.11,43.66) 67.68,41.31 70.1,38.89 arc(70.68,38.5) 71.36,38.37 86.62,38.37 arc(89.14,37.87) 91.27,36.44 98.06,29.65 arc(98.48,29.02) 98.63,28.28 98.63,27.55 arc(98.79,26.74) 99.25,26.04 99.79,25.51 arc(100.21,25.15) 100.69,24.86 arc(101.43,24.6) 102.21,24.51 arc(102.95,24.36) 103.57,23.94 104.85,22.66 arc(105.9,21.96) 107.14,21.71 119.72,21.71 arc(120.61,21.34) 120.98,20.45 120.98,13.31 arc(120.94,13.1) 120.82,12.92 120.69,12.79 arc(120.51,12.67) 120.29,12.62 119.3,12.62 arc(119.07,12.58) 118.88,12.45 118.86,12.43 arc(118.73,12.24) 118.68,12.01 118.68,11.97 arc(118.65,11.81) 118.56,11.68 118.55,11.66 arc(118.46,11.53) 118.42,11.37 J20.11
PCIE0_REFCLKP: length 89.6
  TOP w0.107: J3.201 65.94,54.81 arc(65.93,54.75) 65.9,54.7 65.88,54.69 arc(65.85,54.64) 65.84,54.59 65.84,46.43 arc(66.37,43.77) 67.88,41.52 70.3,39.09 arc(70.79,38.77) 71.37,38.65 86.62,38.65 arc(89.25,38.13) 91.47,36.64 98.26,29.85 arc(98.74,29.13) 98.91,28.28 98.91,27.55 arc(99.05,26.85) 99.45,26.25 99.99,25.71 arc(100.38,25.38) 100.82,25.12 arc(101.49,24.87) 102.21,24.79 arc(103.05,24.62) 103.77,24.14 105.05,22.86 arc(106.01,22.22) 107.14,21.99 119.72,21.99 arc(120.81,21.54) 121.26,20.45 121.26,13.31 arc(121.2,12.99) 121.02,12.72 120.89,12.59 arc(120.61,12.4) 120.29,12.34 119.3,12.34 arc(119.18,12.32) 119.08,12.25 119.06,12.23 arc(118.99,12.13) 118.97,12.01 118.97,11.98 arc(118.99,11.85) 119.06,11.75 119.1,11.71 arc(119.19,11.57) 119.22,11.41 J20.13
PCIE0_RXN: length 90.2
  TOP w0.135: J3.209 67.94,54.7 68.03,54.61 68.03,45.98 arc(68.44,43.93) 69.6,42.2 71.45,40.35 arc(71.63,40.23) 71.86,40.18 87.93,40.18 arc(90.46,39.68) 92.61,38.24 106.57,24.29 arc(107.33,23.78) 108.24,23.6 121.48,23.6 arc(121.71,23.55) 121.91,23.42 121.96,23.36 arc(122.12,23.13) 122.17,22.86 122.17,14.76 arc(122.36,13.83) 122.88,13.05 122.91,13.02 arc(123.7,12.5) 124.62,12.31 126.48,12.31 arc(126.61,12.26) 126.67,12.13 126.67,12.06 arc(126.64,11.91) 126.56,11.79 126.54,11.77 arc(126.45,11.64) 126.42,11.5 J20.23
PCIE0_RXP: length 90.2
  TOP w0.135: J3.211 68.44,54.7 68.35,54.61 68.35,45.98 arc(68.73,44.05) 69.82,42.42 71.67,40.58 arc(71.75,40.52) 71.86,40.5 87.93,40.5 arc(90.58,39.97) 92.83,38.46 106.79,24.51 arc(107.45,24.07) 108.24,23.91 121.48,23.91 arc(121.83,23.84) 122.13,23.64 122.19,23.58 arc(122.41,23.25) 122.49,22.86 122.49,14.76 arc(122.65,13.95) 123.11,13.27 123.13,13.24 arc(123.82,12.78) 124.62,12.62 126.48,12.62 arc(126.84,12.48) 126.98,12.13 126.98,12.06 arc(127.01,11.91) 127.09,11.79 127.11,11.77 arc(127.2,11.64) 127.22,11.5 J20.25
PCIE0_TXN: length 83.3
  TOP w0.135: J3.205 66.94,54.7 67.03,54.61 67.03,49.99 arc(67,49.9) 66.91,49.86 arc(66.81,49.82) 66.78,49.73 66.78,49.31 arc(66.81,49.22) 66.91,49.18 arc(67,49.15) 67.03,49.06 67.03,48.64 arc(67,48.55) 66.91,48.51 arc(66.81,48.47) 66.78,48.38 66.78,47.97 arc(66.81,47.88) 66.91,47.84 arc(67,47.8) 67.03,47.71 67.03,47.29 arc(67,47.2) 66.91,47.17 arc(66.81,47.13) 66.78,47.04 66.78,46.62 arc(66.81,46.53) 66.91,46.49 arc(67,46.45) 67.03,46.36 67.03,45.4 arc(67.4,43.57) 68.43,42.02 70.79,39.67 arc(71.24,39.37) 71.77,39.26 86.87,39.26 arc(89.99,38.64) 92.64,36.87 106.13,23.38 arc(107,22.8) 108.03,22.59 120.49,22.59 arc(120.59,22.55) 120.63,22.46 v1(120.63,22.31) ; v1(123.15,24.15) 123.28,24.15 arc(123.37,24.11) 123.41,24.02 123.41,23.69 arc(123.37,23.47) 123.25,23.29 C170.1
  ART03 w0.135: v1(123.15,24.15) 123.37,24.15 arc(123.49,24.1) 123.54,23.98 123.54,23.14 arc(123.11,22.1) 122.08,21.67 120.3,21.67 arc(120.12,21.75) 120.05,21.92 120.05,22.16 arc(120.12,22.33) 120.29,22.4 120.54,22.4 v1(120.63,22.31)
PCIE0_TXP: length 83.2
  TOP w0.135: v1(123.99,24.15) 123.85,24.01 arc(123.76,23.87) 123.72,23.71 123.72,23.66 arc(123.76,23.48) 123.86,23.32 C171.1 ; J3.207 67.44,54.7 67.35,54.61 67.35,45.4 arc(67.69,43.69) 68.65,42.24 71.01,39.89 arc(71.36,39.65) 71.77,39.57 86.87,39.57 arc(90.11,38.93) 92.86,37.09 106.35,23.6 arc(107.12,23.09) 108.03,22.91 120.22,22.91 arc(120.37,22.94) 120.5,23.02 v1(120.63,23.15)
  ART03 w0.135: v1(120.63,23.15) 120.63,22.89 arc(120.58,22.76) 120.45,22.71 120.29,22.71 arc(119.9,22.55) 119.74,22.16 119.74,21.92 arc(119.9,21.53) 120.3,21.36 122.08,21.36 arc(123.33,21.88) 123.85,23.14 123.85,23.93 arc(123.87,24.01) 123.91,24.07 v1(123.99,24.15)
PCIE0_WAKEN_M0: length 104.1
  TOP w0.107: J3.137 48.44,54.04 v1(48.94,53.54) ; R180.1 103.13,13.47 102.57,12.9 102.57,9.4 v1(101.88,8.71)
  BOTTOM w0.107: v1(101.88,8.71) 90.73,8.71 88.09,11.35 88.09,14 86.65,15.43 75.68,15.43 73.63,13.39 66.85,13.39 65.35,14.88 61.44,14.88 60.15,16.18 60.15,16.56 59.87,16.84 59.11,16.84 52.43,23.52 52.43,25.93 48.86,29.5 48.86,31.98 49.78,32.9 49.78,52.7 v1(48.94,53.54)
PE_TXN: length 17.4
  TOP w0.135: J20.31 129.62,11.54 arc(129.65,11.68) 129.74,11.81 129.78,11.85 arc(129.84,11.95) 129.87,12.06 129.87,12.46 arc(129.63,13.04) 129.06,13.28 124.61,13.28 arc(123.76,13.63) 123.41,14.47 123.41,21.52 arc(123.37,21.74) 123.25,21.92 C170.2
PE_TXP: length 17.4
  TOP w0.135: C171.2 123.89,21.92 arc(123.77,21.74) 123.73,21.52 123.73,14.47 arc(123.98,13.85) 124.61,13.59 129.06,13.59 arc(129.85,13.26) 130.18,12.46 130.18,12.22 130.18,12.06 arc(130.2,11.95) 130.27,11.85 130.31,11.81 arc(130.4,11.68) 130.42,11.54 J20.33
PMIC_EXT_EN: length 25.2
  TOP w0.107: R199.1 14.24,43.92 15.01,43.92 16.18,42.75 22.17,42.75 23.93,44.5 23.93,49.86 23.44,50.35 J3.37
PWM0_CH0_M0_IR: length 134.8
  TOP w0.107: v1(129.92,50.77) 137.41,43.28 137.41,38.73 136.7,38.02 136.7,29.11 137.16,28.65 144.22,28.65 144.98,27.89 147.62,27.89 148.51,27 148.51,10.06 147.47,9.02 141.63,9.02 140.73,8.12 R21.2 R26.1 ; J3.215 69.44,51.93 v1(69.94,51.43)
  BOTTOM w0.107: v1(69.94,51.43) 69.94,51.44 73.13,51.44 77.42,47.14 102.26,47.14 103.89,48.77 109.6,48.77 111.3,47.07 114.58,47.07 115.87,48.36 128.96,48.36 129.92,49.33 v1(129.92,50.77)
PWM2_CH3_M3: length 207.2
  TOP w0.107: J3.122 44.69,62.44 v1(44.69,62.44)
  ART03 w0.107: v1(105.91,8.13) 106.17,8.39 106.17,20.19 104.88,21.49 104.88,37.52 106.86,39.5 108.48,39.5 111.5,42.51 v1(111.5,45.05)
  BOTTOM w0.107: v1(44.69,62.44) 44.69,62.42 44.32,62.05 44.32,61.34 42.55,59.56 42.55,58.98 39.8,56.23 39.8,49.02 40.39,48.44 40.39,36.27 39.14,35.03 39.14,34.11 39.8,33.45 39.8,22.43 41.27,20.96 41.27,10.14 43,8.41 43,5.54 45.36,3.17 64.77,3.17 67.49,5.89 105.11,5.89 105.91,6.7 v1(105.91,8.13) ; v1(111.5,45.05) 112.17,44.37 115.65,44.37 117.22,45.95 129.82,45.95 131.34,47.47 140.52,47.47 144.66,51.61 J32.11
PWM2_CH6_M3: length 210.1
  TOP w0.107: J3.124 v1(45.19,61.44)
  ART03 w0.107: v1(104.91,8.13) 105.01,8.22 105.01,20.14 103.56,21.59 103.56,37.64 107.31,41.4 109.04,41.4 110.54,42.9 110.54,44.72 v1(110.2,45.05)
  BOTTOM w0.107: v1(45.19,61.44) 45.19,61.14 43.28,59.23 43.28,58.75 40.33,55.8 40.33,49.46 40.97,48.82 40.97,33.99 41.48,33.48 41.48,29.34 40.41,28.27 40.41,23.16 41.94,21.62 41.94,10.79 46.23,6.5 46.23,5.11 47.5,3.84 64.49,3.84 67.2,6.55 104.52,6.55 104.91,6.94 v1(104.91,8.13) ; v1(110.2,45.05) 111.19,44.07 116.03,44.07 117.42,45.47 129.92,45.47 131.44,46.99 140.97,46.99 144.32,50.34 145.36,50.34 146.08,51.05 146.08,52.96 J32.10
PWM2_CH7_M3: length 214.5
  TOP w0.107: v1(45.69,62.44) 45.69,62.44 J3.126
  ART03 w0.107: v1(110.2,46.05) 110.92,45.34 110.92,42.62 108.64,40.34 106.96,40.34 104.01,37.39 104.01,21.72 105.41,20.32 v1(105.41,7.13)
  BOTTOM w0.107: v1(105.41,7.13) 105.41,6.83 104.8,6.22 67.36,6.22 64.64,3.51 47.22,3.51 45.87,4.85 45.87,6.3 41.62,10.56 41.62,21.38 40.15,22.85 40.15,33.44 40.67,33.96 40.67,48.66 40.07,49.25 40.07,56 42.93,58.85 42.93,59.44 44.7,61.21 44.7,61.75 45.4,62.44 v1(45.69,62.44) ; v1(110.2,46.05) 110.69,45.57 111.61,45.57 112.47,44.7 115.26,44.7 117.01,46.46 129.62,46.46 131.14,47.98 140.41,47.98 143.59,51.16 143.59,54.89 144.09,55.4 145.97,55.4 J32.8
PWR_3V3_EN: length 77.5
  TOP w0.107: J3.112 42.19,61.75 43.19,60.75 50.19,60.75 v1(50.69,60.25) ; R195.1 59.3,18.67 58.42,18.67 58.24,18.48 58.24,17.65 58.08,17.49 v1(58.08,15.75)
  BOTTOM w0.107: v1(58.08,15.75) 58.08,15.35 55.5,12.78 51.69,12.78 50.91,13.56 50.91,25.22 47.35,28.78 47.35,32.82 48.26,33.73 48.26,50.7 45.59,53.37 45.59,54.38 47.24,56.03 48.9,56.03 50.69,57.83 v1(50.69,60.25)
PWR_5V_EN: length 79.7
  TOP w0.107: J3.110 41.69,61.79 42.99,60.49 48.95,60.49 v1(50.19,59.25) ; v1(58.08,14.75) 57.66,15.16 57.66,17.49 57.83,17.66 57.98,17.81 57.98,18.59 58.32,18.93 59.51,18.93 59.77,18.67 60.33,18.67 R200.1
  BOTTOM w0.107: v1(50.19,59.25) 50.19,57.89 48.69,56.39 47.17,56.39 45.31,54.53 45.31,53.09 47.93,50.47 47.93,33.99 47.02,33.07 47.02,28.58 50.65,24.94 50.65,13.23 51.51,12.37 55.7,12.37 v1(58.08,14.75)
PWR_12V_EN: length 76.9
  TOP w0.107: v1(51.19,59.25) 51.19,60.39 50.57,61.01 43.46,61.01 42.69,61.78 J3.114 ; R193.1 v1(67.78,11.82)
  BOTTOM w0.107: v1(51.19,59.25) 51.44,59.01 51.44,57.13 50.01,55.7 47.47,55.7 46.43,54.66 46.43,53.37 48.67,51.13 48.67,33.45 47.71,32.5 47.71,28.94 51.31,25.35 51.31,23.14 59.08,15.37 59.08,14.94 62.2,11.82 v1(67.78,11.82)
PWR_ON: length 199.9
  TOP w0.107: v1(19.24,43.21) 22.1,43.21 23.5,44.6 23.5,48.77 22.23,50.04 22.23,52.96 22.44,53.18 J3.33
  ART03 w0.107: v1(100.94,36.4) 101.47,35.86 101.47,26.21 92.21,16.94 76.17,16.94 75.97,17.14 60.38,17.14 59.36,18.16 54.23,18.16 53.95,17.88 44.07,17.88 42.57,16.38 36.7,16.38 34.8,18.29 21.73,18.29 v1(21.48,18.54)
  BOTTOM w0.107: Q12.3 17.95,44.5 v1(19.24,43.21) 20.93,41.51 20.93,19.48 21.48,18.93 v1(21.48,18.54) ; v1(100.94,36.4) 104.17,36.4 106.88,39.12 106.88,41.05 109.7,43.87 109.7,46.18 110.08,46.56 114.86,46.56 116.18,47.88 129.16,47.88 130.58,49.3 130.58,62.05 128.27,64.36 R31.2
RECOVERY: length 19.6
  BOTTOM w0.107: R30.1 C27.1 132.29,66.24 133.71,66.24 D12.2 135.74,68.28 139.24,68.28 143.13,72.16 143.13,74.78 SW2.2
RECOVERY_KEY: length 211.4
  TOP w0.107: J3.96 38.19,61.68 v1(39.62,60.25)
  ART03 w0.107: v1(112.5,46.05) 112.78,45.77 112.78,41.48 110.82,39.52 110.19,39.52 106.35,35.69 106.35,22.35 107.7,21.01 107.7,9.04 108.41,8.33 v1(108.41,7.13)
  BOTTOM w0.107: R30.2 130.68,63.3 130.96,63.02 130.96,49.07 129.26,47.37 116.46,47.37 115.14,46.05 112.5,46.05 v1(112.5,46.05) ; v1(39.62,60.25) 40.03,59.84 40.03,57.92 38.96,56.85 38.96,48.84 38.35,48.23 38.35,36.2 37.41,35.26 37.41,31.01 38.05,30.38 38.05,27.99 37.01,26.95 37.01,23.65 40.14,20.52 40.14,9.72 41.94,7.92 41.94,5 44.81,2.13 65.2,2.13 67.97,4.9 106.19,4.9 v1(108.41,7.13)
RK806_VDC: length 3.5
  TOP w0.107: R198.1 22.94,52.52 J3.35
RMII0_AVDD33: length 17.5
  TOP w0.203: v1(63.67,32.19) U7.11 ; U7.40 v1(68.67,32.18)
  TOP w0.381: v1(70.96,27.52) 70.96,27.29 72.26,25.98 C46.1 72.78,25.61 L5.2
  BOTTOM w0.254: v1(68.67,32.18) C47.1 68.67,30.68 68.39,30.4 64.31,30.4 63.67,31.05 C48.1 v1(63.67,32.19)
  BOTTOM w0.381: v1(70.96,27.52) 70.96,28.3 70.24,29.02 R52.2 68.67,29.66 68.67,30.12 68.39,30.4
RMII0_LED1: length 173
  TOP w0.107: v1(126.59,57.99) 125.67,57.06 125.67,52.49 117.67,44.49 v1(117.67,40.99)
  TOP w0.203: v1(74.43,27) 74.43,27.01 R56.1 C150.1 72.31,27.01 71.25,28.07 70.61,28.07 69.76,28.92 U7.33
  BOTTOM w0.107: v1(117.67,40.99) 116.28,39.6 112.01,39.6 111.23,38.81 111.23,36.63 108.84,34.24 108.31,34.24 107.95,33.88 107.95,33.48 106.06,31.58 98.69,31.58 93.62,26.52 91.52,26.52 91.06,26.06 76.56,26.06 75.62,27 v1(74.43,27) ; J6.14 56.93,86 59,83.92 92.02,83.92 93.72,85.63 102.66,85.63 104.65,83.64 104.65,74.96 110.95,68.66 110.95,67.79 110.46,67.31 110.46,60.53 113.43,57.56 126.16,57.56 v1(126.59,57.99)
RMII0_LED2: length 157.2
  TOP w0.107: v1(116.67,40.99) 117.17,41.48 117.17,44.49 125.31,52.63 125.31,57.71 v1(125.59,57.99)
  TOP w0.203: v1(72,28.35) 71.82,28.52 70.66,28.52 69.87,29.32 U7.34
  BOTTOM w0.107: J6.11 71.07,84.28 91.73,84.28 93.53,86.08 102.87,86.08 105,83.95 105,75.25 111.3,68.95 111.3,67.67 110.82,67.18 110.82,60.68 113.51,57.99 v1(125.59,57.99) ; v1(116.67,40.99) 115.64,39.95 111.81,39.95 110.9,39.04 110.9,36.93 108.64,34.67 107.82,34.67 105.13,31.98 98.32,31.98 93.8,27.46 91.82,27.46 90.75,26.39 76.83,26.39 75.67,27.56 74.12,27.56 R54.1 C149.1 72.32,28.35 v1(72,28.35)
RMII0_MDIN0: length 45.2
  TOP w0.107: v1(67.77,36.23) 67.91,36.08 67.91,34.03 67.62,33.74 67.62,32.95 67.57,32.9 U7.2
  BOTTOM w0.107: v1(67.77,36.23) 67.37,36.63 67.37,39.1 64.25,42.23 64.25,57.52 66.93,60.2 66.93,72.82 66.57,73.18 66.04,73.18 65.91,73.04 J6.3
RMII0_MDIN1: length 52.7
  TOP w0.107: v1(66.77,36.23) 66.9,36.1 66.9,34 66.42,33.53 66.42,32.97 66.37,32.92 U7.5
  BOTTOM w0.107: J6.7 60.83,72.22 60.83,75.13 61.47,75.77 62.81,75.77 63.17,75.41 63.17,73.89 64.49,72.57 64.49,70.39 66.16,68.71 66.16,60.52 63.48,57.84 63.48,41.91 66.37,39.01 66.37,36.63 v1(66.77,36.23)
RMII0_MDIN2: length 46.2
  TOP w0.107: v1(65.27,36.23) 65.62,35.87 65.62,32.96 65.57,32.9 U7.7
  BOTTOM w0.107: v1(65.27,36.23) 64.87,36.63 64.87,39.24 62.71,41.41 62.71,58.16 65.39,60.84 65.39,63.52 64.41,64.49 64.41,68.73 61.92,71.23 61.92,74.57 J6.6
RMII0_MDIN3: length 47.5
  TOP w0.107: U7.10 64.37,32.9 64.42,32.95 64.42,36.08 v1(64.28,36.22)
  BOTTOM w0.107: J6.9 58.29,73.04 58.45,73.2 58.88,73.2 59.46,72.62 59.46,70.87 60.23,70.1 61.4,70.1 63.49,68 63.49,63.94 64.62,62.81 64.62,61.16 61.94,58.48 61.94,41.01 63.77,39.18 63.77,36.74 v1(64.28,36.22)
RMII0_MDIP0: length 45.1
  TOP w0.107: v1(67.78,37.03) 68.2,36.62 68.2,33.91 67.91,33.62 67.91,32.93 67.97,32.87 U7.1
  BOTTOM w0.107: J6.2 67.22,74.71 67.22,60.09 64.54,57.4 64.54,42.34 67.66,39.22 67.66,37.16 v1(67.78,37.03)
RMII0_MDIP1: length 52.8
  TOP w0.107: U7.4 66.77,32.9 66.71,32.96 66.71,33.41 67.18,33.88 67.18,36.63 v1(66.78,37.03)
  BOTTOM w0.107: J6.4 64.64,73.9 64.8,73.74 65.53,73.74 65.63,73.84 65.63,75.23 65.13,75.74 63.93,75.74 63.45,75.27 63.45,74.01 64.77,72.69 64.77,70.5 66.45,68.83 66.45,60.41 63.76,57.72 63.76,42.02 66.66,39.13 66.66,37.16 v1(66.78,37.03)
RMII0_MDIP2: length 46.1
  TOP w0.107: v1(65.28,37.03) 65.91,36.4 65.91,32.95 65.97,32.89 U7.6
  BOTTOM w0.107: v1(65.28,37.03) 65.16,37.16 65.16,39.36 62.99,41.53 62.99,58.04 65.67,60.73 65.67,63.63 64.7,64.61 64.7,68.85 62.2,71.34 62.2,72.95 62.33,73.08 62.87,73.08 63.37,72.58 J6.5
RMII0_MDIP3: length 47.4
  TOP w0.107: v1(64.28,37.03) 64.71,36.6 64.71,32.95 64.77,32.9 U7.9
  BOTTOM w0.107: J6.8 59.74,74.56 59.74,70.99 60.35,70.38 61.52,70.38 63.78,68.12 63.78,64.05 64.9,62.93 64.9,61.05 62.22,58.36 62.22,41.13 64.05,39.29 64.05,37.26 v1(64.28,37.03)
RMII0_VDD10: length 22.5
  TOP w0.203: U7.8 v1(65.17,33.2) ; U7.21 64.37,26.98 63.5,26.11 62.22,26.11 C38.1 ; U7.38 69.45,30.92 v1(69.72,31.19) ; v1(67.17,33.2) 67.17,33.05 67.17,33.05 U7.3
  TOP w0.254: C37.1 v1(68.32,20.19) ; v1(62.96,26.86) 62.65,26.86 62.22,26.44 C38.1
  BOTTOM w0.254: v1(69.72,31.19) 69.72,32 68.86,32.87 67.5,32.87 v1(67.17,33.2) 67.17,33.18 66.67,32.68 C40.1 C39.1 65.67,32.7 v1(65.17,33.2) 63.93,33.2 62.99,32.26 62.99,30.68 63.5,30.18 63.5,27.4 v1(62.96,26.86)
RMII1_AVDD33: length 17.5
  TOP w0.203: U8.40 v1(84.9,32.18) ; U8.11 v1(79.9,32.18)
  TOP w0.381: v1(87.19,27.52) 87.19,27.29 88.49,25.98 C62.1 89.01,25.61 L7.2
  BOTTOM w0.254: v1(84.9,32.18) C64.1 84.9,30.71 84.62,30.43 80.41,30.43 79.9,30.94 C63.1 v1(79.9,32.18)
  BOTTOM w0.381: v1(87.19,27.52) 87.19,28.18 86.34,29.02 R76.2 84.9,29.66 84.9,30.15 84.62,30.43
RMII1_LED1: length 137.1
  TOP w0.107: v1(126.59,58.99) 126.18,59.4 125.26,59.4 124.52,58.66 124.52,53 116.15,44.63 116.15,41.47 v1(115.67,40.99)
  TOP w0.203: v1(90.72,27) 90.71,27.01 R80.1 C147.1 88.54,27.01 87.55,27.99 86.89,27.99 85.96,28.92 U8.33
  BOTTOM w0.107: v1(126.59,58.99) 126.02,58.42 113.61,58.42 111.18,60.86 111.18,66.98 111.61,67.41 111.61,69.33 105.36,75.57 105.36,84.15 102.94,86.57 93.33,86.57 91.53,84.76 76.87,84.76 J7.14 ; v1(115.67,40.99) 114.98,40.3 111.59,40.3 110.64,39.34 110.64,37.33 108.38,35.08 107.57,35.08 104.9,32.41 98.17,32.41 93.57,27.81 91.53,27.81 v1(90.72,27)
RMII1_LED2: length 119.5
  TOP w0.107: v1(116.67,41.99) 116.67,44.59 124.9,52.82 124.9,58.3 v1(125.59,58.99)
  TOP w0.203: v1(88.3,28.35) 88.13,28.52 86.97,28.52 86.17,29.32 U8.34
  BOTTOM w0.107: v1(125.59,58.99) 125.38,58.78 113.76,58.78 111.55,60.99 111.55,66.8 111.94,67.18 111.94,69.57 105.75,75.76 105.75,84.34 103.05,87.05 92.99,87.05 91.94,86 J7.11 ; v1(116.67,41.99) 116.11,41.43 115.42,41.43 114.63,40.64 111.43,40.64 110.24,39.45 110.24,37.46 108.26,35.48 107.42,35.48 104.8,32.87 98.04,32.87 93.65,28.47 90.49,28.47 90.04,28.02 R79.1 C144.1 88.65,28.35 v1(88.3,28.35)
RMII1_MDIN0: length 67.1
  TOP w0.107: v1(84,36.23) 84.12,36.11 84.12,34.06 83.86,33.79 83.86,33.08 83.8,33.02 U8.2
  BOTTOM w0.107: v1(84,36.23) 83.6,36.63 83.6,37.86 80.85,40.61 71.88,40.61 68.06,44.44 68.06,48.5 68.55,48.99 68.55,51.9 68.06,52.39 68.06,56.09 70.2,58.24 70.2,63.24 75.72,68.76 80.8,68.76 82.42,70.38 84.18,70.38 85.01,71.22 85.9,71.22 86.56,71.88 86.56,72.88 86.31,73.13 85.65,73.13 85.44,72.91 J7.3
RMII1_MDIN1: length 72.2
  TOP w0.107: v1(83,36.23) 83.13,36.1 83.13,34.06 82.65,33.57 82.65,33.07 82.6,33.02 U8.5
  BOTTOM w0.107: v1(83,36.23) 82.6,36.63 82.6,37.46 80.31,39.75 71.48,39.75 67.28,43.95 67.28,49.09 67.69,49.5 67.69,51.39 67.28,51.79 67.28,56.41 69.43,58.56 69.43,63.56 75.4,69.53 80.32,69.53 82,71.2 83.62,71.2 84.02,71.6 84.02,72.75 82.75,74.02 82.75,75.26 82.26,75.76 80.94,75.76 80.36,75.18 J7.7
